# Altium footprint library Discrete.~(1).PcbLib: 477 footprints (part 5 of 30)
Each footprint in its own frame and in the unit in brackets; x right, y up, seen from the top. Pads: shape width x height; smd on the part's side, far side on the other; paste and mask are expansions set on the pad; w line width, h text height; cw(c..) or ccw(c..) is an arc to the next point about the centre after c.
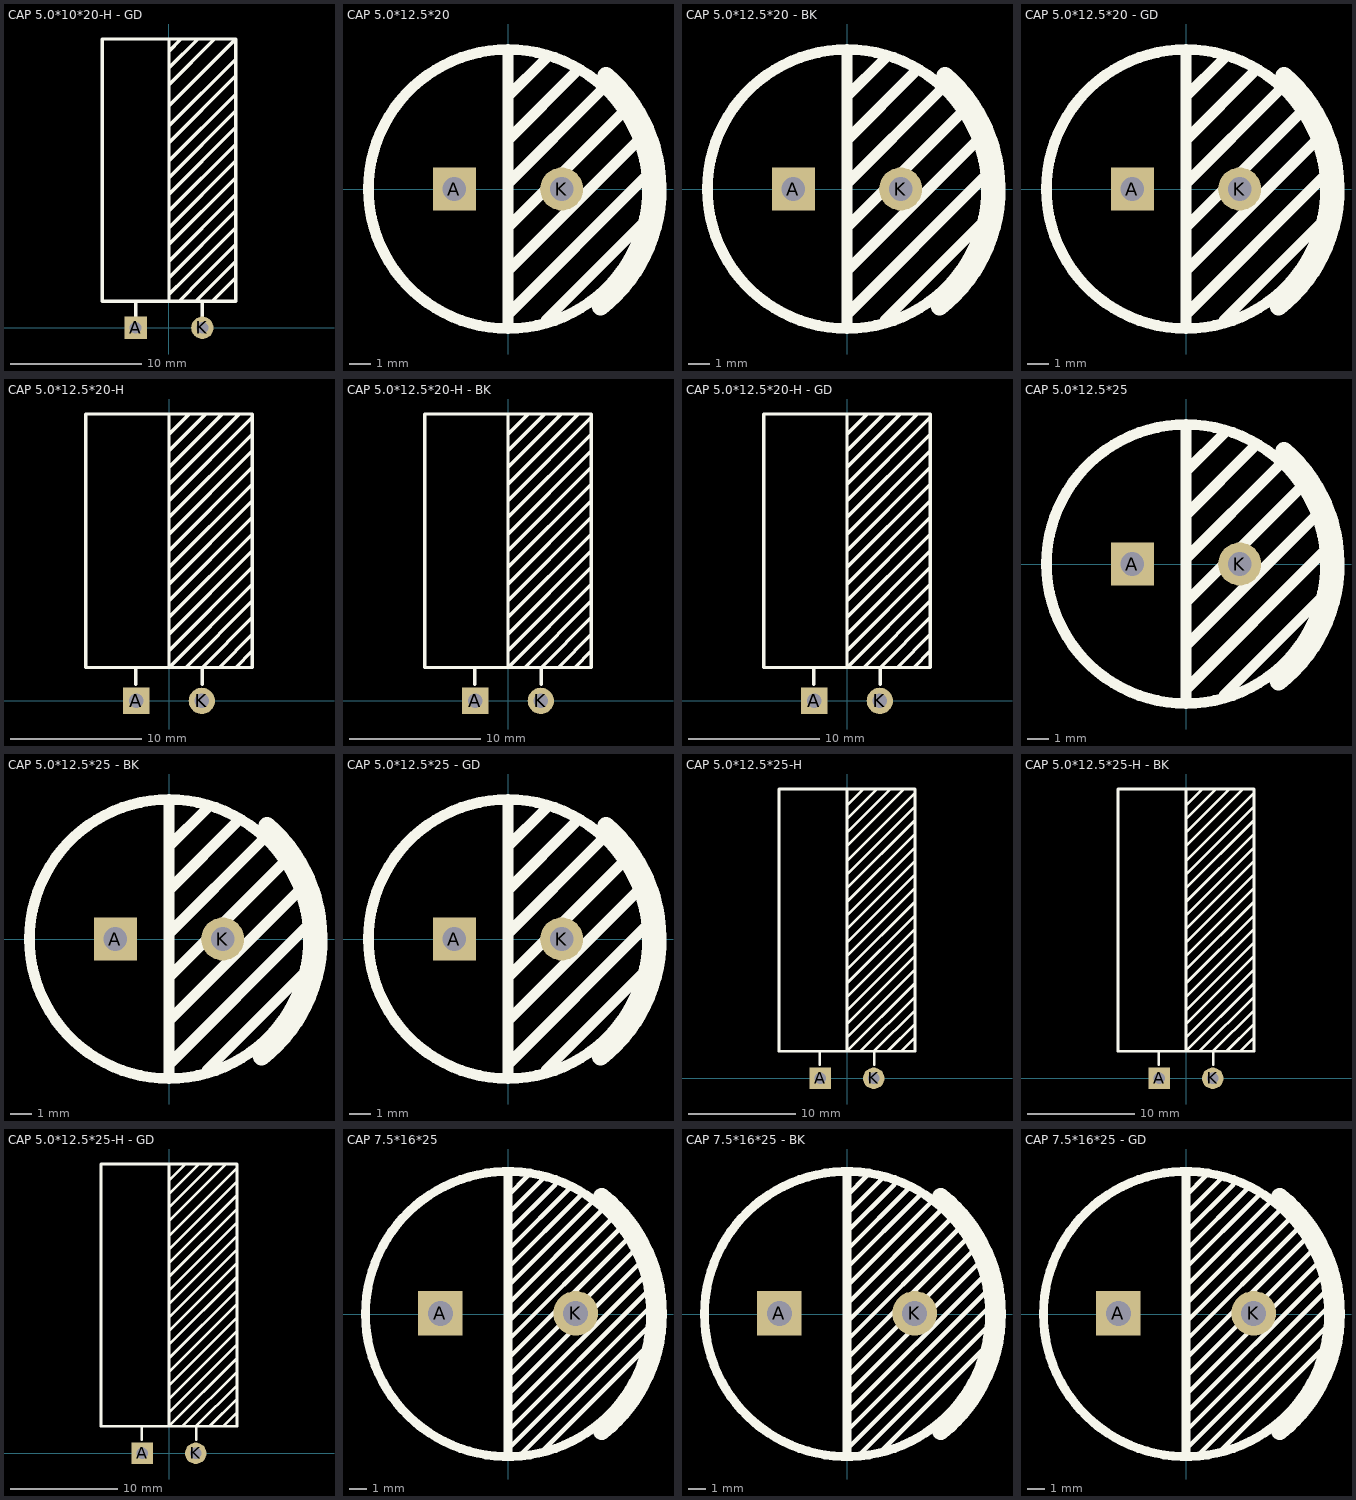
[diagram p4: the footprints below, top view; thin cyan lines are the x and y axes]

## CAP 5.0*10*20-H - GD [mm] "脚距5mm直径10mm高度20mm"
pads (2):
  rect 1.7x1.7 hole 0.9: A(-2.54,0)
  round 1.7 hole 0.9: K(2.54,0)
Top Overlay:
  lines w0.254: -2.54,0.762 -2.54,1.778 -2.54,2.032 ; 0,2.032 0,2.54 ; 0,4.064 0,2.54 ; 0,5.08 5.08,10.16 ; 0,6.35 5.08,11.43 ; 0,7.62 5.08,12.7 ; 0,8.89 5.08,13.97 ; 0,10.16 5.08,15.24 ; 0,11.43 5.08,16.51 ; 0,12.7 5.08,17.78 ; 0,14.097 5.08,19.177 ; 0,15.367 5.08,20.447 ; 0,16.891 5.08,21.971 ; 0,18.5 3.45,21.95 ; 0,19.77 2.18,21.95 ; 0,21.04 0.91,21.95 ; 0,21.971 0,3.81 5.08,8.89 ; 0.762,2.032 2.54,3.81 5.08,6.35 ; 2.032,2.032 3.81,3.81 5.08,5.08 ; 2.54,0.762 2.54,1.778 2.54,2.032 ; 3.302,2.032 5.08,3.81 ; 5.08,7.62 1.27,3.81 0,2.54 ; 5.08,21.971 5.08,2.032 -5.08,2.032 -5.08,21.971 5.08,21.971
3D body "CAP 5X10X20-H.STEP": height 10.03, standoff -3.48, extent -5.04,-0.3 4.97,21.91

## CAP 5.0*12.5*20 [mm] "脚距5mm直径12.5mm高度20mm"
pads (2):
  rect 2x2 hole 1.1: A(-2.5,0)
  round 2 hole 1.1: K(2.5,0)
Top Overlay:
  circle w0.5: c0,0 r6.5
  lines w0.5: 0,-5.08 0,-3.81 6.096,2.286 ; 0,-2.54 0,-1.778 5.334,3.556 ; 0,0 0,0.254 4.318,4.572 ; 0,1.016 0,2.286 3.302,5.588 ; 0,3.048 0,4.064 ; 0,4.318 1.778,6.096 ; 0,6.35 0,-6.35 0,-5.842 6.35,0.508 ; 1.778,-6.096 6.35,-1.524
  lines w0.8: 4.307,-5.503 ccw(c0,0) 4.568,5.289
3D body "CAP 5X12.5X20.STEP": height 20.03, standoff -3.38, extent -6.25,-6.248 6.26,6.248

## CAP 5.0*12.5*20 - BK [mm] "脚距5mm直径12.5mm高度20mm"
pads (2):
  rect 2x2 hole 1.1: A(-2.5,0)
  round 2 hole 1.1: K(2.5,0)
Top Overlay:
  circle w0.5: c0,0 r6.5
  lines w0.5: 0,-5.08 0,-3.81 6.096,2.286 ; 0,-2.54 0,-1.778 5.334,3.556 ; 0,0 0,0.254 4.318,4.572 ; 0,1.016 0,2.286 3.302,5.588 ; 0,3.048 0,4.064 ; 0,4.318 1.778,6.096 ; 0,6.35 0,-6.35 0,-5.842 6.35,0.508 ; 1.778,-6.096 6.35,-1.524
  lines w0.8: 4.307,-5.503 ccw(c0,0) 4.568,5.289
3D body "CAP 5X12.5X20.STEP": height 20.04, standoff -3.37, extent -6.25,-6.248 6.26,6.248

## CAP 5.0*12.5*20 - GD [mm] "脚距5mm直径12.5mm高度20mm"
pads (2):
  rect 2x2 hole 1.1: A(-2.5,0)
  round 2 hole 1.1: K(2.5,0)
Top Overlay:
  circle w0.5: c0,0 r6.5
  lines w0.5: 0,-5.08 0,-3.81 6.096,2.286 ; 0,-2.54 0,-1.778 5.334,3.556 ; 0,0 0,0.254 4.318,4.572 ; 0,1.016 0,2.286 3.302,5.588 ; 0,3.048 0,4.064 ; 0,4.318 1.778,6.096 ; 0,6.35 0,-6.35 0,-5.842 6.35,0.508 ; 1.778,-6.096 6.35,-1.524
  lines w0.8: 4.307,-5.503 ccw(c0,0) 4.568,5.289
3D body "CAP 5X12.5X20.STEP": height 20.04, standoff -3.37, extent -6.25,-6.248 6.26,6.248

## CAP 5.0*12.5*20-H [mm] "脚距5mm直径12.5mm高度20mm"
pads (2):
  rect 2x2 hole 1.1: A(-2.5,0)
  round 2 hole 1.1: K(2.5,0)
Top Overlay:
  lines w0.254: -2.54,1.27 -2.54,2.54 ; 0,3.81 6.35,10.16 ; 0,5.08 6.35,11.43 ; 0,6.35 6.35,12.7 ; 0,7.62 6.35,13.97 ; 0,8.89 6.35,15.24 ; 0,10.16 6.35,16.51 ; 0,11.43 6.35,17.78 ; 0,12.7 6.35,19.05 ; 0,13.97 6.35,20.32 ; 0,15.24 6.35,21.59 ; 0,16.51 5.334,21.844 ; 0,17.78 4.064,21.844 ; 0,19.05 2.794,21.844 ; 0,20.32 1.524,21.844 ; 0,21.844 0,2.54 6.35,8.89 ; 1.27,2.54 6.35,7.62 ; 2.54,1.27 2.54,2.54 6.35,6.35 ; 3.81,2.54 6.35,5.08 ; 5.08,2.54 6.35,3.81 ; -6.35,2.54 -6.35,21.844 6.35,21.844 6.35,2.54 -6.35,2.54
3D body "CAP 5X12.5X20-H.STEP": height 12.53, standoff -3.47, extent -6.25,-0.3 6.26,21.91

## CAP 5.0*12.5*20-H - BK [mm] "脚距5mm直径12.5mm高度20mm"
pads (2):
  rect 2x2 hole 1.1: A(-2.5,0)
  round 2 hole 1.1: K(2.5,0)
Top Overlay:
  lines w0.254: -2.54,1.27 -2.54,2.54 ; 0,3.81 6.35,10.16 ; 0,5.08 6.35,11.43 ; 0,6.35 6.35,12.7 ; 0,7.62 6.35,13.97 ; 0,8.89 6.35,15.24 ; 0,10.16 6.35,16.51 ; 0,11.43 6.35,17.78 ; 0,12.7 6.35,19.05 ; 0,13.97 6.35,20.32 ; 0,15.24 6.35,21.59 ; 0,16.51 5.334,21.844 ; 0,17.78 4.064,21.844 ; 0,19.05 2.794,21.844 ; 0,20.32 1.524,21.844 ; 0,21.844 0,2.54 6.35,8.89 ; 1.27,2.54 6.35,7.62 ; 2.54,1.27 2.54,2.54 6.35,6.35 ; 3.81,2.54 6.35,5.08 ; 5.08,2.54 6.35,3.81 ; -6.35,2.54 -6.35,21.844 6.35,21.844 6.35,2.54 -6.35,2.54
3D body "CAP 5X12.5X20-H.STEP": height 12.53, standoff -3.48, extent -6.25,-0.3 6.26,21.91

## CAP 5.0*12.5*20-H - GD [mm] "脚距5mm直径12.5mm高度20mm"
pads (2):
  rect 2x2 hole 1.1: A(-2.5,0)
  round 2 hole 1.1: K(2.5,0)
Top Overlay:
  lines w0.254: -2.54,1.27 -2.54,2.54 ; 0,3.81 6.35,10.16 ; 0,5.08 6.35,11.43 ; 0,6.35 6.35,12.7 ; 0,7.62 6.35,13.97 ; 0,8.89 6.35,15.24 ; 0,10.16 6.35,16.51 ; 0,11.43 6.35,17.78 ; 0,12.7 6.35,19.05 ; 0,13.97 6.35,20.32 ; 0,15.24 6.35,21.59 ; 0,16.51 5.334,21.844 ; 0,17.78 4.064,21.844 ; 0,19.05 2.794,21.844 ; 0,20.32 1.524,21.844 ; 0,21.844 0,2.54 6.35,8.89 ; 1.27,2.54 6.35,7.62 ; 2.54,1.27 2.54,2.54 6.35,6.35 ; 3.81,2.54 6.35,5.08 ; 5.08,2.54 6.35,3.81 ; -6.35,2.54 -6.35,21.844 6.35,21.844 6.35,2.54 -6.35,2.54
3D body "CAP 5X12.5X20-H.STEP": height 12.53, standoff -3.48, extent -6.25,-0.3 6.26,21.91

## CAP 5.0*12.5*25 [mm] "脚距5mm直径12.5mm高度25mm"
pads (2):
  rect 2x2 hole 1.1: A(-2.5,0)
  round 2 hole 1.1: K(2.5,0)
Top Overlay:
  circle w0.5: c0,0 r6.5
  lines w0.5: 0,-5.08 0,-3.81 6.096,2.286 ; 0,-2.54 0,-1.778 5.334,3.556 ; 0,0 0,0.254 4.318,4.572 ; 0,1.016 0,2.286 3.302,5.588 ; 0,3.048 0,4.064 ; 0,4.318 1.778,6.096 ; 0,6.35 0,-6.35 0,-5.842 6.35,0.508 ; 1.778,-6.096 6.35,-1.524
  lines w0.8: 4.307,-5.503 ccw(c0,0) 4.568,5.289
3D body "CAP 5X12.5X25.STEP": height 25.04, standoff -3.37, extent -6.25,-6.249 6.26,6.249

## CAP 5.0*12.5*25 - BK [mm] "脚距5mm直径12.5mm高度25mm"
pads (2):
  rect 2x2 hole 1.1: A(-2.5,0)
  round 2 hole 1.1: K(2.5,0)
Top Overlay:
  circle w0.5: c0,0 r6.5
  lines w0.5: 0,-5.08 0,-3.81 6.096,2.286 ; 0,-2.54 0,-1.778 5.334,3.556 ; 0,0 0,0.254 4.318,4.572 ; 0,1.016 0,2.286 3.302,5.588 ; 0,3.048 0,4.064 ; 0,4.318 1.778,6.096 ; 0,6.35 0,-6.35 0,-5.842 6.35,0.508 ; 1.778,-6.096 6.35,-1.524
  lines w0.8: 4.307,-5.503 ccw(c0,0) 4.568,5.289
3D body "CAP 5X12.5X25.STEP": height 25.04, standoff -3.37, extent -6.25,-6.249 6.26,6.249

## CAP 5.0*12.5*25 - GD [mm] "脚距5mm直径12.5mm高度25mm"
pads (2):
  rect 2x2 hole 1.1: A(-2.5,0)
  round 2 hole 1.1: K(2.5,0)
Top Overlay:
  circle w0.5: c0,0 r6.5
  lines w0.5: 0,-5.08 0,-3.81 6.096,2.286 ; 0,-2.54 0,-1.778 5.334,3.556 ; 0,0 0,0.254 4.318,4.572 ; 0,1.016 0,2.286 3.302,5.588 ; 0,3.048 0,4.064 ; 0,4.318 1.778,6.096 ; 0,6.35 0,-6.35 0,-5.842 6.35,0.508 ; 1.778,-6.096 6.35,-1.524
  lines w0.8: 4.307,-5.503 ccw(c0,0) 4.568,5.289
3D body "CAP 5X12.5X25.STEP": height 25.06, standoff -3.35, extent -6.239,-6.244 6.271,6.254

## CAP 5.0*12.5*25-H [mm] "脚距5mm直径12.5mm高度25mm"
pads (2):
  rect 2x2 hole 1.1: A(-2.5,0)
  round 2 hole 1.1: K(2.5,0)
Top Overlay:
  lines w0.254: -2.54,1.27 -2.54,2.54 ; 0,3.81 6.35,10.16 ; 0,5.08 6.35,11.43 ; 0,6.35 6.35,12.7 ; 0,7.62 6.35,13.97 ; 0,8.89 6.35,15.24 ; 0,10.16 6.35,16.51 ; 0,11.43 6.35,17.78 ; 0,12.7 6.35,19.05 ; 0,13.97 6.35,20.32 ; 0,15.24 6.35,21.59 ; 0,16.51 6.35,22.86 ; 0,17.78 6.35,24.13 ; 0,19.05 6.35,25.4 ; 0,20.32 6.35,26.67 ; 0,21.717 5.334,27.051 ; 0,22.987 4.064,27.051 ; 0,24.257 2.794,27.051 ; 0,25.527 1.524,27.051 ; 0,27.051 0,2.54 6.35,8.89 ; 1.27,2.54 6.35,7.62 ; 2.54,1.27 2.54,2.54 6.35,6.35 ; 3.81,2.54 6.35,5.08 ; 5.08,2.54 6.35,3.81 ; -6.35,2.54 6.35,2.54 6.35,27.051 -6.35,27.051 -6.35,2.54
3D body "CAP 5X12.5X25-H.STEP": height 12.53, standoff -3.47, extent -6.25,-0.3 6.26,26.91

## CAP 5.0*12.5*25-H - BK [mm] "脚距5mm直径12.5mm高度25mm"
pads (2):
  rect 2x2 hole 1.1: A(-2.5,0)
  round 2 hole 1.1: K(2.5,0)
Top Overlay:
  lines w0.254: -2.54,1.27 -2.54,2.54 ; 0,3.81 6.35,10.16 ; 0,5.08 6.35,11.43 ; 0,6.35 6.35,12.7 ; 0,7.62 6.35,13.97 ; 0,8.89 6.35,15.24 ; 0,10.16 6.35,16.51 ; 0,11.43 6.35,17.78 ; 0,12.7 6.35,19.05 ; 0,13.97 6.35,20.32 ; 0,15.24 6.35,21.59 ; 0,16.51 6.35,22.86 ; 0,17.78 6.35,24.13 ; 0,19.05 6.35,25.4 ; 0,20.32 6.35,26.67 ; 0,21.717 5.334,27.051 ; 0,22.987 4.064,27.051 ; 0,24.257 2.794,27.051 ; 0,25.527 1.524,27.051 ; 0,27.051 0,2.54 6.35,8.89 ; 1.27,2.54 6.35,7.62 ; 2.54,1.27 2.54,2.54 6.35,6.35 ; 3.81,2.54 6.35,5.08 ; 5.08,2.54 6.35,3.81 ; -6.35,2.54 -6.35,27.051 6.35,27.051 6.35,2.54 -6.35,2.54
3D body "CAP 5X12.5X25-H.STEP": height 12.53, standoff -3.48, extent -6.25,-0.3 6.26,26.91

## CAP 5.0*12.5*25-H - GD [mm] "脚距5mm直径12.5mm高度25mm"
pads (2):
  rect 2x2 hole 1.1: A(-2.5,0)
  round 2 hole 1.1: K(2.5,0)
Top Overlay:
  lines w0.254: -2.54,1.27 -2.54,2.54 ; 0,3.81 6.35,10.16 ; 0,5.08 6.35,11.43 ; 0,6.35 6.35,12.7 ; 0,7.62 6.35,13.97 ; 0,8.89 6.35,15.24 ; 0,10.16 6.35,16.51 ; 0,11.43 6.35,17.78 ; 0,12.7 6.35,19.05 ; 0,13.97 6.35,20.32 ; 0,15.24 6.35,21.59 ; 0,16.51 6.35,22.86 ; 0,17.78 6.35,24.13 ; 0,19.05 6.35,25.4 ; 0,20.32 6.35,26.67 ; 0,21.717 5.334,27.051 ; 0,22.987 4.064,27.051 ; 0,24.257 2.794,27.051 ; 0,25.527 1.524,27.051 ; 0,27.051 0,2.54 6.35,8.89 ; 1.27,2.54 6.35,7.62 ; 2.54,1.27 2.54,2.54 6.35,6.35 ; 3.81,2.54 6.35,5.08 ; 5.08,2.54 6.35,3.81 ; -6.35,2.54 -6.35,27.051 6.35,27.051 6.35,2.54 -6.35,2.54
3D body "CAP 5X12.5X25-H.STEP": height 12.53, standoff -3.48, extent -6.25,-0.3 6.26,26.91

## CAP 7.5*16*25 [mm] "脚距7.5mm直径16mm高度25mm"
pads (2):
  rect 2.5x2.5 hole 1.4: A(-3.8,0.038)
  round 2.5 hole 1.4: K(3.8,0.038)
Top Overlay:
  circle w0.5: c0,0 r8
  lines w0.254: 0,-7.582 8.001,0.419 ; 0,-6.566 7.874,1.308 ; 0,-5.55 7.62,2.07 ; 0,-4.534 7.366,2.832 ; 0,-3.518 6.972,3.454 ; 0,-2.502 6.604,4.102 ; 0,-1.486 6.223,4.737 ; 0,-0.47 5.905,5.436 ; 0,0.546 5.296,5.842 ; 0,1.562 4.826,6.388 ; 0,2.578 4.064,6.642 ; 0,3.594 3.556,7.15 ; 0,4.61 2.54,7.15 2.769,7.379 ; 0,5.626 2.032,7.658 ; 0,6.642 1.143,7.785 ; 0.66,-7.938 7.938,-0.66 ; 2.032,-7.582 6.604,-3.01 7.81,-1.803
  lines w0.5: 0,-7.963 0,7.963
  lines w1: 5.259,-6.574 ccw(c0,0) 5.259,6.574
3D body "CAP 7.5X16X25.STEP": height 25.03, standoff -3.38, extent -8,-7.999 8.01,7.999

## CAP 7.5*16*25 - BK [mm] "脚距7.5mm直径16mm高度25mm"
pads (2):
  rect 2.5x2.5 hole 1.4: A(-3.8,0.038)
  round 2.5 hole 1.4: K(3.8,0.038)
Top Overlay:
  circle w0.5: c0,0 r8
  lines w0.254: 0,-7.582 8.001,0.419 ; 0,-6.566 7.874,1.308 ; 0,-5.55 7.62,2.07 ; 0,-4.534 7.366,2.832 ; 0,-3.518 6.972,3.454 ; 0,-2.502 6.604,4.102 ; 0,-1.486 6.223,4.737 ; 0,-0.47 5.905,5.436 ; 0,0.546 5.296,5.842 ; 0,1.562 4.826,6.388 ; 0,2.578 4.064,6.642 ; 0,3.594 3.556,7.15 ; 0,4.61 2.54,7.15 2.769,7.379 ; 0,5.626 2.032,7.658 ; 0,6.642 1.143,7.785 ; 0.66,-7.938 7.938,-0.66 ; 2.032,-7.582 6.604,-3.01 7.81,-1.803
  lines w0.5: 0,-7.963 0,7.963
  lines w1: 5.259,-6.574 ccw(c0,0) 5.259,6.574
3D body "CAP 7.5X16X25.STEP": height 25.04, standoff -3.37, extent -8,-7.999 8.01,7.999

## CAP 7.5*16*25 - GD [mm] "脚距7.5mm直径16mm高度25mm"
pads (2):
  rect 2.5x2.5 hole 1.4: A(-3.8,0.038)
  round 2.5 hole 1.4: K(3.8,0.038)
Top Overlay:
  circle w0.5: c0,0 r8
  lines w0.254: 0,-7.582 8.001,0.419 ; 0,-6.566 7.874,1.308 ; 0,-5.55 7.62,2.07 ; 0,-4.534 7.366,2.832 ; 0,-3.518 6.972,3.454 ; 0,-2.502 6.604,4.102 ; 0,-1.486 6.223,4.737 ; 0,-0.47 5.905,5.436 ; 0,0.546 5.296,5.842 ; 0,1.562 4.826,6.388 ; 0,2.578 4.064,6.642 ; 0,3.594 3.556,7.15 ; 0,4.61 2.54,7.15 2.769,7.379 ; 0,5.626 2.032,7.658 ; 0,6.642 1.143,7.785 ; 0.66,-7.938 7.938,-0.66 ; 2.032,-7.582 6.604,-3.01 7.81,-1.803
  lines w0.5: 0,-7.963 0,7.963
  lines w1: 5.259,-6.574 ccw(c0,0) 5.259,6.574
3D body "CAP 7.5X16X25.STEP": height 25.04, standoff -3.37, extent -8,-7.999 8.01,7.999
